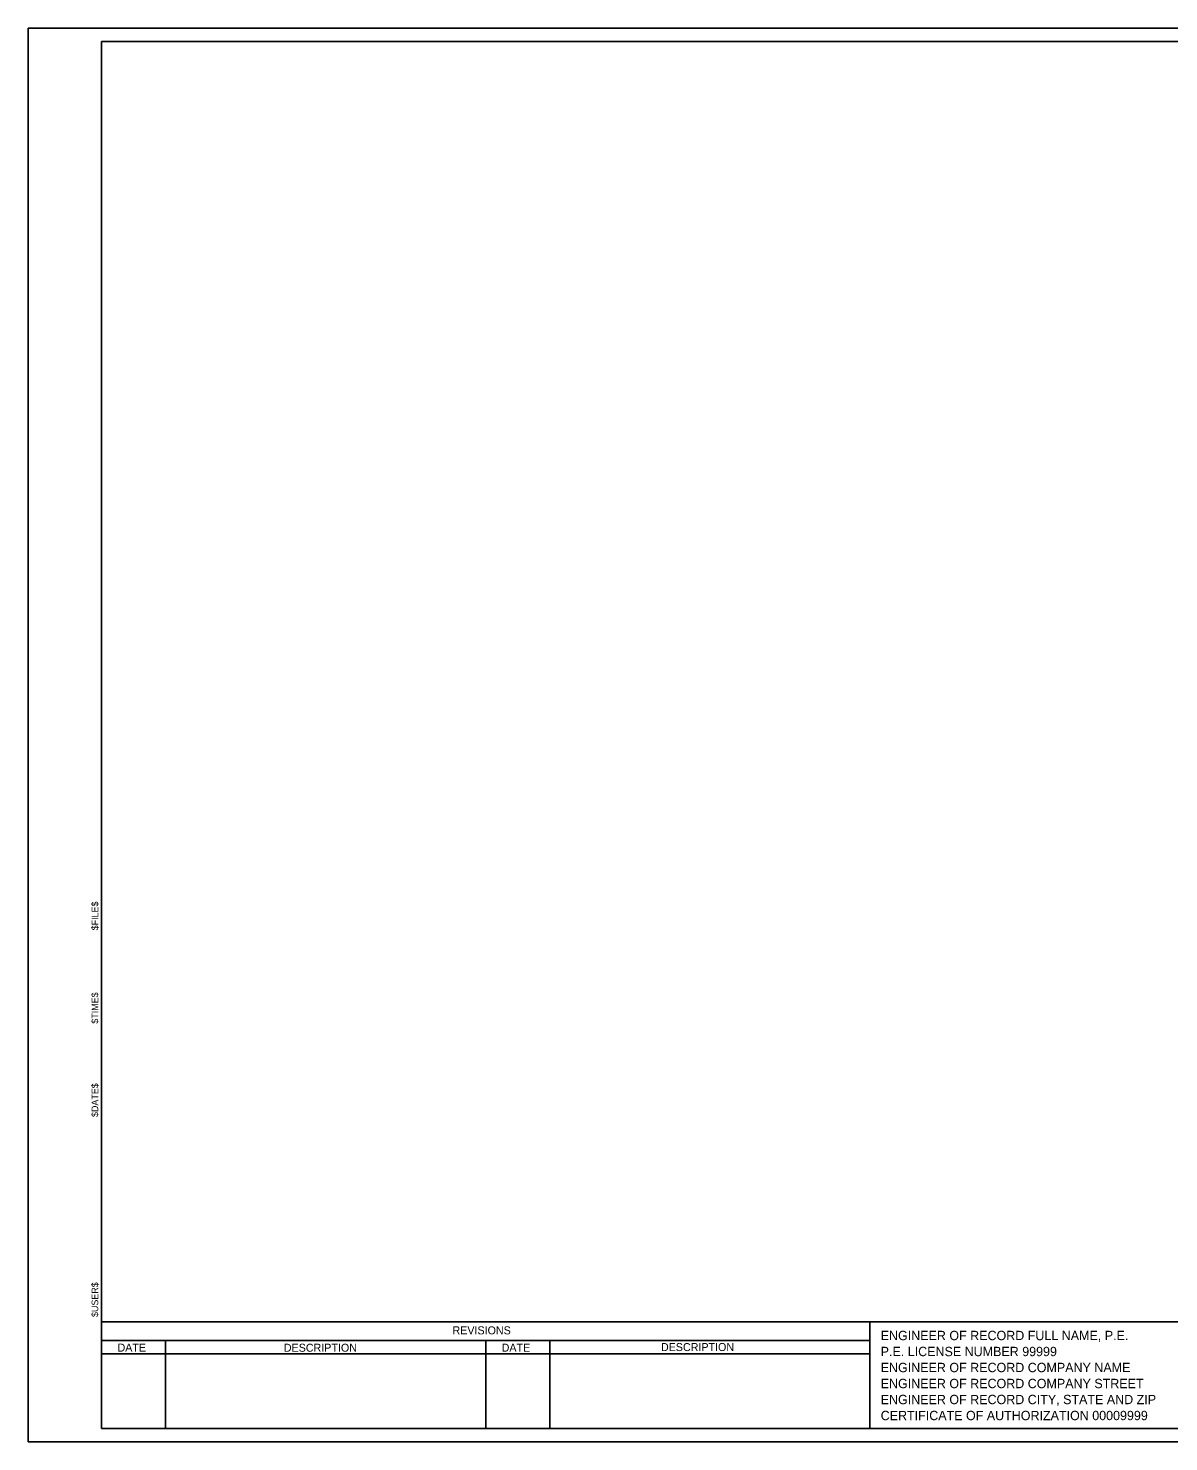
# Model space of a CAD drawing. Extents: x -863 to -203, y -614 to -190.
# Drawn here: x -862.5 to -520.5, y -614.1 to -190.1 of the extents above; entities that cross this region are included whole.
import ezdxf

# ---------------------------------------------------------------- set-up
doc = ezdxf.new("R2010")
doc.units = 0
for name, color, linetype in [('AdhocPoint_dp', 7, 'Continuous'), ('PlotBorder_dp', 7, 'Continuous'), ('SheetBorder_dp', 7, 'Continuous'), ('SheetLines_dp', 7, 'Continuous'), ('TextMinor', 7, 'Continuous'), ('TextMisc', 7, 'Continuous'), ('TextNotes', 7, 'Continuous')]:
    doc.layers.add(name, color=color, linetype=linetype)

msp = doc.modelspace()

# ---------------------------------------------------------------- linework, layer by layer
at = {"layer": 'AdhocPoint_dp'}
msp.add_line((-862.51, -614.11), (-862.51, -614.11), dxfattribs=at)
at = {"layer": 'PlotBorder_dp'}
msp.add_lwpolyline([(-862.51, -614.11), (-202.51, -614.11), (-202.51, -190.11), (-862.51, -190.11)], close=True, dxfattribs=at)
at = {"layer": 'SheetBorder_dp'}
for p, q in [((-840.51, -194.11), (-840.51, -610.11)), ((-840.51, -194.11), (-224.51, -194.11)), ((-840.51, -578.11), (-224.51, -578.11)), ((-840.51, -610.11), (-224.51, -610.11))]:
    msp.add_line(p, q, dxfattribs=at)
at = {"layer": 'SheetLines_dp'}
for p, q in [((-610.11, -578.11), (-610.11, -610.11)), ((-840.51, -583.71), (-610.11, -583.71)), ((-821.31, -583.71), (-821.31, -610.11)), ((-725.31, -583.71), (-725.31, -610.11)), ((-706.11, -583.71), (-706.11, -610.11)), ((-840.51, -587.71), (-610.11, -587.71))]:
    msp.add_line(p, q, dxfattribs=at)

# ---------------------------------------------------------------- texts
at = {"layer": 'TextMinor'}
for s, p in [('$FILE$', (-841.53, -460.69)), ('$TIME$', (-841.53, -488.69)), ('$DATE$', (-841.53, -516.69)), ('$USER$', (-841.53, -576.69))]:
    msp.add_text(s, height=2, rotation=90, dxfattribs=at).set_placement(p)
at = {"layer": 'TextMisc'}
for s, rotation, p in [('REVISIONS', 360, (-735.29, -581.9)), ('DATE', 359.8693, (-835.75, -587.07)), ('DESCRIPTION', 0.0498, (-785.87, -587.12)), ('DATE', 359.8693, (-720.55, -587.09)), ('DESCRIPTION', 0.0498, (-672.77, -586.92))]:
    msp.add_text(s, height=2.4, rotation=rotation, dxfattribs=at).set_placement(p)
at = {"layer": 'TextNotes'}
for s, p in [('ENGINEER OF RECORD FULL NAME, P.E.    ', (-606.88, -583.64)), ('P.E. LICENSE NUMBER 99999', (-606.88, -588.44)), ('ENGINEER OF RECORD COMPANY NAME       ', (-606.88, -593.24)), ('ENGINEER OF RECORD COMPANY STREET     ', (-606.88, -598.04)), ('ENGINEER OF RECORD CITY, STATE AND ZIP', (-606.88, -602.84)), ('CERTIFICATE OF AUTHORIZATION 00009999', (-606.88, -607.64))]:
    msp.add_text(s, height=2.8, dxfattribs=at).set_placement(p)

doc.saveas('drawing.dxf')
